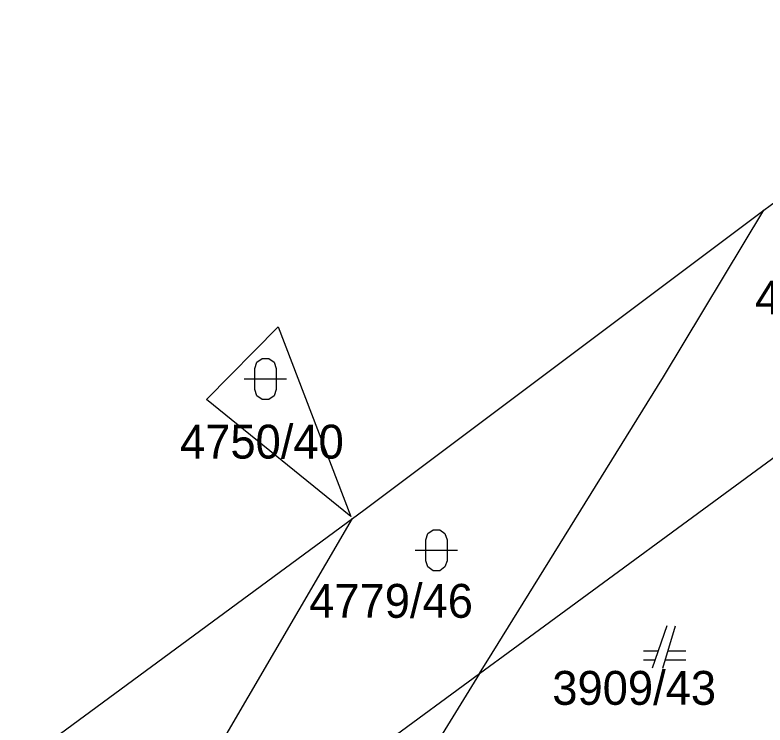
# Model space of a CAD drawing. Extents: x -266179 to -264727, y -1243225 to -1241702.
# Drawn here: x -265270.6 to -265235.19, y -1242855.08 to -1242821.55 of the extents above; entities that cross this region are included whole.
import ezdxf

# ---------------------------------------------------------------- set-up
doc = ezdxf.new("R2010")
doc.units = 0
doc.layers.add('Vrstva 1', color=7, linetype='Continuous')

msp = doc.modelspace()

# ---------------------------------------------------------------- linework, layer by layer
at = {"layer": 'Vrstva 1'}
for p, q in [((-265235.24, -1242830.77), (-265222.95, -1242821.55)), ((-265254.13, -1242844.94), (-265235.24, -1242830.77)), ((-265239.99, -1242838.64), (-265235.24, -1242830.77)), ((-265247.08, -1242851.49), (-265224.78, -1242835.1)), ((-265261.56, -1242839.71), (-265258.18, -1242836.28)), ((-265258.18, -1242836.28), (-265254.74, -1242845.24)), ((-265248.07, -1242851.69), (-265239.99, -1242838.64)), ((-265254.74, -1242845.24), (-265261.56, -1242839.71)), ((-265254.66, -1242845.33), (-265254.13, -1242844.94)), ((-265270.6, -1242857.06), (-265254.66, -1242845.33)), ((-265266, -1242864.74), (-265254.66, -1242845.33)), ((-265239.82, -1242850.4), (-265240.52, -1242852.4)), ((-265240.02, -1242852.4), (-265239.42, -1242850.4)), ((-265248.67, -1242852.65), (-265247.08, -1242851.49)), ((-265248.67, -1242852.65), (-265248.07, -1242851.69)), ((-265240.24, -1242851.6), (-265240.92, -1242851.6)), ((-265238.92, -1242851.6), (-265239.78, -1242851.6)), ((-265240.92, -1242852), (-265240.38, -1242852)), ((-265239.9, -1242852), (-265238.92, -1242852)), ((-265266.63, -1242865.82), (-265248.67, -1242852.65)), ((-265248.67, -1242852.65), (-265259.73, -1242870.53))]:
    msp.add_line(p, q, dxfattribs=at)
for points in [[(-265259.28, -1242838.24), (-265259.18, -1242837.95), (-265258.93, -1242837.77), (-265258.62, -1242837.77), (-265258.37, -1242837.95), (-265258.27, -1242838.24), (-265258.27, -1242839.24), (-265258.37, -1242839.53), (-265258.62, -1242839.71), (-265258.93, -1242839.71), (-265259.18, -1242839.53), (-265259.28, -1242839.24)], [(-265251.21, -1242846.33), (-265251.11, -1242846.04), (-265250.86, -1242845.86), (-265250.55, -1242845.86), (-265250.3, -1242846.04), (-265250.2, -1242846.33), (-265250.2, -1242847.33), (-265250.3, -1242847.62), (-265250.55, -1242847.8), (-265250.86, -1242847.8), (-265251.11, -1242847.62), (-265251.21, -1242847.33)]]:
    msp.add_lwpolyline(points, close=True, dxfattribs=at)
for points in [[(-265259.78, -1242838.74), (-265258.51, -1242838.74), (-265257.78, -1242838.74)], [(-265251.71, -1242846.83), (-265250.44, -1242846.83), (-265249.71, -1242846.83)]]:
    msp.add_lwpolyline(points, dxfattribs=at)

# ---------------------------------------------------------------- texts
for s, p in [('4779/45', (-265235.657, -1242835.69)), ('4750/40', (-265262.81, -1242842.5)), ('4779/46', (-265256.712, -1242850.02)), ('3909/43', (-265245.233, -1242854.13))]:
    msp.add_text(s, height=1.6, dxfattribs=at).set_placement(p)

doc.saveas('drawing.dxf')
